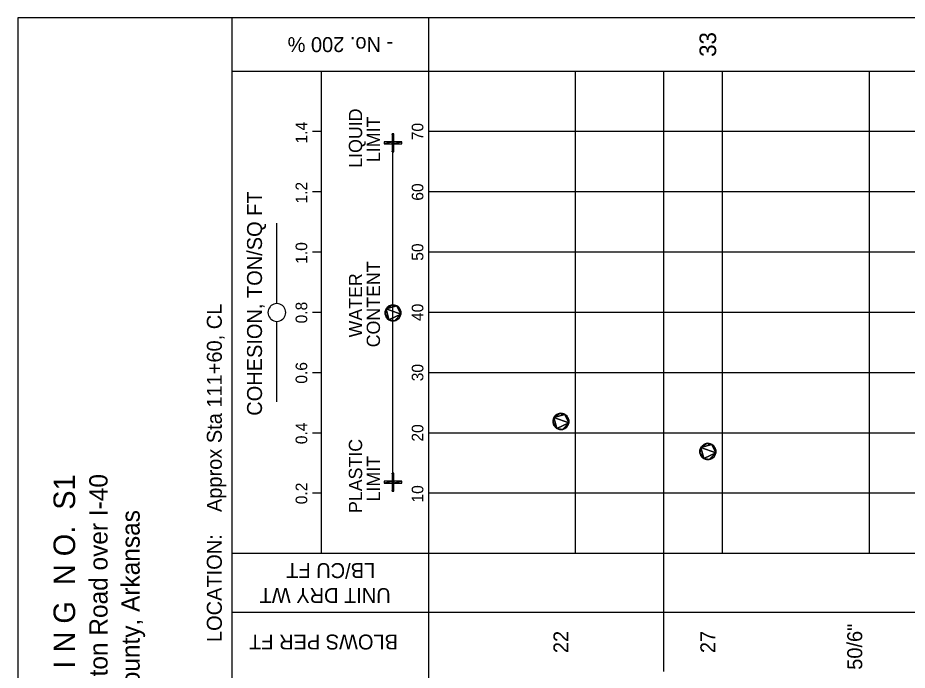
# Model space of a CAD drawing. Extents: x 1313964 to 1316843, y 2087046 to 2096619.
# Drawn here: x 1313975.39 to 1314005.66, y 2089894.09 to 2089916.31 of the extents above; entities that cross this region are included whole.
import ezdxf

# ---------------------------------------------------------------- set-up
doc = ezdxf.new("R2010")
doc.units = 0
doc.layers.add('B-Sub-Contour', color=7, linetype='Continuous')
doc.layers.add('Default', color=7, linetype='Continuous')

# ---------------------------------------------------------------- blocks, each defined once
blk = doc.blocks.new('POINT_DISPLAY')
at = {"layer": 'Default'}
blk.add_line((0, 0), (0, 0), dxfattribs=at)
blk = doc.blocks.new('DMK_101')
at = {"layer": 'Default'}
for points in [[(-14269.212, 2386.584), (-14476.476, 0), (-14269.212, -2386.584), (-14269.212, 2386.584)], [(-12638.532, 6858), (-13653.516, 4690.872), (-14269.212, 2386.584), (-12638.532, 6858)], [(-12638.532, 6858), (-14269.212, 2386.584), (-14269.212, -2386.584), (-12638.532, 6858)], [(-12638.532, 6858), (-14269.212, -2386.584), (-3147.06, -13508.736), (-12638.532, 6858)], [(-3147.06, 13511.784), (-7618.476, 11878.056), (-12638.532, 6858), (-3147.06, 13511.784)], [(6097.524, 11878.056), (-3147.06, 13511.784), (-12638.532, 6858), (6097.524, 11878.056)], [(-7618.476, 11878.056), (-11266.932, 8820.912), (-12638.532, 6858), (-7618.476, 11878.056)], [(-3147.06, -13508.736), (6097.524, 11878.056), (-12638.532, 6858), (-3147.06, -13508.736)], [(-7618.476, 11878.056), (-9578.34, 10506.456), (-11266.932, 8820.912), (-7618.476, 11878.056)], [(-9578.34, 10506.456), (-10456.164, 9698.736), (-11266.932, 8820.912), (-9578.34, 10506.456)], [(-3147.06, 13511.784), (-5451.348, 12893.04), (-7618.476, 11878.056), (-3147.06, 13511.784)], [(1626.108, 13511.784), (-760.476, 13712.952), (-3147.06, 13511.784), (1626.108, 13511.784)], [(6097.524, 11878.056), (1626.108, 13511.784), (-3147.06, 13511.784), (6097.524, 11878.056)], [(-3147.06, -13508.736), (11117.58, -6858), (6097.524, 11878.056), (-3147.06, -13508.736)], [(6097.524, 11878.056), (3930.396, 12893.04), (1626.108, 13511.784), (6097.524, 11878.056)], [(11117.58, 6858), (8060.436, 10506.456), (6097.524, 11878.056), (11117.58, 6858)], [(12751.308, 2386.584), (11117.58, 6858), (6097.524, 11878.056), (12751.308, 2386.584)], [(11117.58, -6858), (12751.308, 2386.584), (6097.524, 11878.056), (11117.58, -6858)], [(9745.98, 8820.912), (8938.26, 9698.736), (8060.436, 10506.456), (9745.98, 8820.912)], [(11117.58, 6858), (9745.98, 8820.912), (8060.436, 10506.456), (11117.58, 6858)], [(12751.308, 2386.584), (12132.564, 4690.872), (11117.58, 6858), (12751.308, 2386.584)], [(11117.58, -6858), (12751.308, -2386.584), (12751.308, 2386.584), (11117.58, -6858)], [(12751.308, -2386.584), (12952.476, 0), (12751.308, 2386.584), (12751.308, -2386.584)], [(-14269.212, -2386.584), (-13653.516, -4690.872), (-12638.532, -6858), (-14269.212, -2386.584)], [(-14269.212, -2386.584), (-12638.532, -6858), (-9578.34, -10506.456), (-14269.212, -2386.584)], [(-14269.212, -2386.584), (-9578.34, -10506.456), (-3147.06, -13508.736), (-14269.212, -2386.584)], [(-12638.532, -6858), (-11266.932, -8817.864), (-9578.34, -10506.456), (-12638.532, -6858)], [(-11266.932, -8817.864), (-10456.164, -9695.688), (-9578.34, -10506.456), (-11266.932, -8817.864)], [(-9578.34, -10506.456), (-7618.476, -11878.056), (-3147.06, -13508.736), (-9578.34, -10506.456)], [(-7618.476, -11878.056), (-5451.348, -12893.04), (-3147.06, -13508.736), (-7618.476, -11878.056)], [(-3147.06, -13508.736), (6097.524, -11878.056), (11117.58, -6858), (-3147.06, -13508.736)], [(-3147.06, -13508.736), (1626.108, -13508.736), (6097.524, -11878.056), (-3147.06, -13508.736)], [(-3147.06, -13508.736), (-760.476, -13716), (1626.108, -13508.736), (-3147.06, -13508.736)], [(1626.108, -13508.736), (3930.396, -12893.04), (6097.524, -11878.056), (1626.108, -13508.736)], [(6097.524, -11878.056), (8060.436, -10506.456), (11117.58, -6858), (6097.524, -11878.056)], [(8060.436, -10506.456), (9745.98, -8817.864), (11117.58, -6858), (8060.436, -10506.456)], [(8060.436, -10506.456), (8938.26, -9695.688), (9745.98, -8817.864), (8060.436, -10506.456)], [(11117.58, -6858), (12132.564, -4690.872), (12751.308, -2386.584), (11117.58, -6858)]]:
    blk.add_lwpolyline(points, close=True, dxfattribs=at)
blk.add_blockref('POINT_DISPLAY', (14479.524, 0), dxfattribs=at)
blk = doc.blocks.new('DMK_7')
at = {"layer": 'Default'}
blk.add_lwpolyline([(0, -15240), (2651.76, -15011.4), (5212.08, -14325.6), (7620, -13197.84), (9799.32, -11673.84), (10774.68, -10774.68), (11673.84, -9799.32), (13197.84, -7620), (14325.6, -5212.08), (15011.4, -2651.76), (15240, 0), (15011.4, 2651.76), (14325.6, 5212.08), (13197.84, 7620), (11673.84, 9799.32), (10774.68, 10774.68), (9799.32, 11673.84), (7620, 13197.84), (5212.08, 14325.6), (2651.76, 15011.4), (0, 15240), (-2651.76, 15011.4), (-5212.08, 14325.6), (-7620, 13197.84), (-9799.32, 11673.84), (-10774.68, 10774.68), (-11673.84, 9799.32), (-13197.84, 7620), (-14325.6, 5212.08), (-15011.4, 2651.76), (-15240, 0), (-15011.4, -2651.76), (-14325.6, -5212.08), (-13197.84, -7620), (-11673.84, -9799.32), (-10774.68, -10774.68), (-9799.32, -11673.84), (-7620, -13197.84), (-5212.08, -14325.6), (-2651.76, -15011.4), (0, -15240)], dxfattribs=at)
blk = doc.blocks.new('DMK_99')
at = {"layer": 'Default'}
for points in [[(1524, 1524), (1524, 15240), (-1524, 15240), (1524, 1524)], [(1524, 1524), (-1524, 15240), (-1524, 1524), (1524, 1524)], [(-1524, -1524), (-1524, 1524), (-15240, 1524), (-1524, -1524)], [(-1524, -1524), (-15240, 1524), (-15240, -1524), (-1524, -1524)], [(-1524, -1524), (1524, -1524), (1524, 1524), (-1524, -1524)], [(-1524, -1524), (1524, 1524), (-1524, 1524), (-1524, -1524)], [(1524, -1524), (15240, -1524), (15240, 1524), (1524, -1524)], [(1524, -1524), (15240, 1524), (1524, 1524), (1524, -1524)], [(-1524, -1524), (-1524, -15240), (1524, -15240), (-1524, -1524)], [(-1524, -1524), (1524, -15240), (1524, -1524), (-1524, -1524)]]:
    blk.add_lwpolyline(points, close=True, dxfattribs=at)

msp = doc.modelspace()

# ---------------------------------------------------------------- linework, layer by layer
at = {"layer": 'B-Sub-Contour'}
for points in [[(1314036.804, 2089873.434), (1314036.804, 2089916.306), (1313975.385, 2089916.306), (1313975.385, 2089873.434), (1314036.804, 2089873.434)], [(1313982.683, 2089873.434), (1313982.683, 2089916.306)], [(1313989.372, 2089873.434), (1313989.372, 2089916.306)], [(1314034.372, 2089914.481), (1313982.683, 2089914.481)], [(1313985.723, 2089914.481), (1313985.419, 2089914.481)], [(1313985.723, 2089898.063), (1313985.723, 2089914.481)], [(1314034.372, 2089914.481), (1313989.372, 2089914.481)], [(1313989.372, 2089898.063), (1313989.372, 2089914.481)], [(1313994.372, 2089898.063), (1313994.372, 2089914.481)], [(1313997.372, 2089894.049), (1313997.372, 2089914.481)], [(1313999.372, 2089898.063), (1313999.372, 2089914.481)], [(1314004.372, 2089898.063), (1314004.372, 2089914.481)], [(1313985.723, 2089912.429), (1313985.419, 2089912.429)], [(1314034.372, 2089912.429), (1313989.372, 2089912.429)], [(1313988.155, 2089900.495), (1313988.155, 2089912.049)], [(1313985.723, 2089910.377), (1313985.419, 2089910.377)], [(1314034.372, 2089910.377), (1313989.372, 2089910.377)], [(1313984.203, 2089906.576), (1313984.203, 2089909.313)], [(1313985.723, 2089908.324), (1313985.419, 2089908.324)], [(1314034.372, 2089908.324), (1313989.372, 2089908.324)], [(1313985.723, 2089906.272), (1313985.419, 2089906.272)], [(1314034.372, 2089906.272), (1313989.372, 2089906.272)], [(1313984.203, 2089903.232), (1313984.203, 2089905.968)], [(1313985.723, 2089904.22), (1313985.419, 2089904.22)], [(1314034.372, 2089904.22), (1313989.372, 2089904.22)], [(1313985.723, 2089902.167), (1313985.419, 2089902.167)], [(1314034.372, 2089902.167), (1313989.372, 2089902.167)], [(1313985.723, 2089900.115), (1313985.419, 2089900.115)], [(1314034.372, 2089900.115), (1313989.372, 2089900.115)], [(1314034.372, 2089898.063), (1313982.683, 2089898.063)], [(1313985.723, 2089898.063), (1313985.419, 2089898.063)], [(1314034.372, 2089898.063), (1313989.372, 2089898.063)], [(1314034.372, 2089896.056), (1313982.683, 2089896.056)]]:
    msp.add_lwpolyline(points, dxfattribs=at)

# ---------------------------------------------------------------- block references
at = {"layer": 'B-Sub-Contour', "xscale": 1.9951013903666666e-05, "yscale": 1.9951013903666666e-05, "rotation": 90}
for name, p in [('DMK_99', (1313988.155, 2089912.049)), ('DMK_7', (1313984.203, 2089906.272)), ('DMK_101', (1313988.155, 2089906.272)), ('DMK_101', (1313993.872, 2089902.578)), ('DMK_101', (1313993.872, 2089902.578)), ('DMK_101', (1313998.872, 2089901.552)), ('DMK_101', (1313998.872, 2089901.552)), ('DMK_99', (1313988.155, 2089900.495))]:
    msp.add_blockref(name, p, dxfattribs=at)

# ---------------------------------------------------------------- texts
at = {"layer": 'B-Sub-Contour'}
for s, height, rotation, p in [('- No. 200 %', 0.50899, 180, (1313988.163, 2089915.648)), ('33', 0.5655, 90, (1313999.154, 2089914.977)), ('LIQUID', 0.4524, 90, (1313987.105, 2089911.2)), ('LIMIT', 0.4524, 90, (1313987.713, 2089911.394)), ('1.4', 0.3959, 90, (1313985.237, 2089912.028)), ('70', 0.3959, 90, (1313989.189, 2089912.138)), ('1.2', 0.3959, 90, (1313985.237, 2089909.983)), ('60', 0.3959, 90, (1313989.189, 2089910.078)), ('COHESION, TON/SQ FT', 0.50899, 90, (1313983.697, 2089902.756)), ('1.0', 0.3959, 90, (1313985.237, 2089907.93)), ('50', 0.3959, 90, (1313989.189, 2089908.033)), ('CONTENT', 0.4524, 90, (1313987.713, 2089905.087)), ('WATER', 0.4524, 90, (1313987.105, 2089905.423)), ('0.8', 0.3959, 90, (1313985.237, 2089905.9)), ('LOCATION:    Approx Sta 111+60, CL', 0.50899, 90, (1313982.329, 2089895.052)), ('40', 0.3959, 90, (1313989.189, 2089905.981)), ('0.6', 0.3959, 90, (1313985.237, 2089903.848)), ('30', 0.3959, 90, (1313989.189, 2089903.929)), ('0.4', 0.3959, 90, (1313985.237, 2089901.788)), ('20', 0.3959, 90, (1313989.189, 2089901.876)), ('PLASTIC', 0.4524, 90, (1313987.105, 2089899.445)), ('LIMIT', 0.4524, 90, (1313987.713, 2089899.84)), ('L O G  O F  B O R I N G  N O.  S1', 0.7352, 90, (1313977.337, 2089885.845)), ('061610 - Remington Road over I-40', 0.62209, 90, (1313978.44, 2089887.499)), ('0.2', 0.3959, 90, (1313985.237, 2089899.743)), ('10', 0.3959, 90, (1313989.189, 2089899.802)), ('Lonoke County, Arkansas', 0.62209, 90, (1313979.534, 2089890.018)), ('LB/CU FT', 0.509, 180, (1313987.549, 2089897.739)), ('UNIT DRY WT', 0.50899, 180, (1313988.078, 2089896.888)), ('22', 0.509, 90, (1313994.126, 2089894.674)), ('27', 0.509, 90, (1313999.126, 2089894.674)), ('50/6"', 0.509, 90, (1314004.126, 2089894.107)), ('BLOWS PER FT', 0.50899, 180, (1313988.324, 2089895.307))]:
    msp.add_text(s, height=height, rotation=rotation, dxfattribs=at).set_placement(p)

doc.saveas('drawing.dxf')
